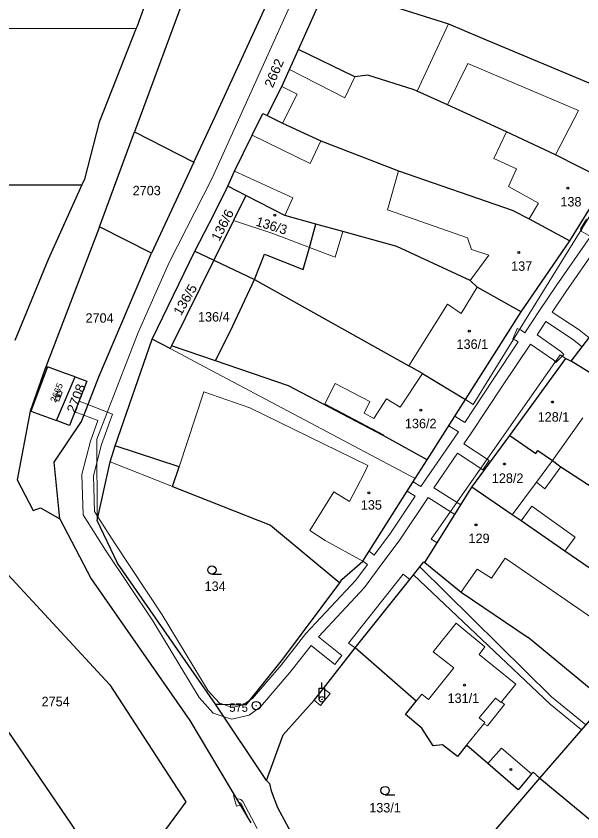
# Model space of a CAD drawing. Extents: x -606517 to -602431, y -1183120 to -1179397.
# Drawn here: x -605631 to -605529.1, y -1181145.3 to -1181000.2 of the extents above; entities that cross this region are included whole.
import ezdxf
from ezdxf.enums import TextEntityAlignment as Align

# ---------------------------------------------------------------- set-up
doc = ezdxf.new("R2010")
doc.units = 0
doc.header["$LTSCALE"] = 0.68
for name, color, linetype, lineweight in [('1', 7, 'Continuous', 25), ('13', 7, 'Continuous', 13), ('3', 7, 'Continuous', 25), ('4', 7, 'Continuous', 13), ('5', 7, 'Continuous', 25), ('6', 7, 'Continuous', 25), ('8', 7, 'Continuous', 25)]:
    doc.layers.add(name, color=color, linetype=linetype, lineweight=lineweight)
doc.layers.add('2', color=7, linetype='Continuous')

msp = doc.modelspace()

# ---------------------------------------------------------------- linework, layer by layer
at = {"layer": '1'}
for p, q in [((-605599.33, -1180975.13), (-605609.21, -1181002.01)), ((-605596.9, -1180986.39), (-605609.67, -1181021.03)), ((-605595.15, -1181018.31), (-605580.95, -1180987.38)), ((-605580.12, -1181006.24), (-605574.98, -1180994.69)), ((-605574.98, -1180994.69), (-605553.1, -1181001.62)), ((-605553.1, -1181001.62), (-605547.49, -1181004.03)), ((-605776.96, -1181002.53), (-605609.37, -1181002.41)), ((-605609.37, -1181002.41), (-605616.01, -1181019.28)), ((-605609.21, -1181002.01), (-605609.37, -1181002.41)), ((-605547.49, -1181004.03), (-605524.08, -1181013.81)), ((-605581.77, -1181009.85), (-605580.12, -1181006.24)), ((-605570.02, -1181011.17), (-605580.12, -1181006.24)), ((-605583.12, -1181012.9), (-605581.77, -1181009.85)), ((-605567.66, -1181010.84), (-605570.02, -1181011.17)), ((-605559.28, -1181013.49), (-605567.66, -1181010.84)), ((-605585.76, -1181018.1), (-605583.12, -1181012.9)), ((-605558.75, -1181013.72), (-605559.28, -1181013.49)), ((-605553.29, -1181016.16), (-605558.75, -1181013.72)), ((-605542.68, -1181021.07), (-605553.29, -1181016.16)), ((-605588.49, -1181021.64), (-605586.54, -1181017.75)), ((-605586.54, -1181017.75), (-605585.76, -1181018.1)), ((-605598.96, -1181026.49), (-605595.15, -1181018.31)), ((-605585.76, -1181018.1), (-605583, -1181019.51)), ((-605616.01, -1181019.28), (-605618.69, -1181029.59)), ((-605583, -1181019.51), (-605576.12, -1181022.66)), ((-605615.97, -1181038.14), (-605609.67, -1181021.03)), ((-605609.67, -1181021.03), (-605598.96, -1181026.49)), ((-605591.63, -1181028.13), (-605588.49, -1181021.64)), ((-605533.83, -1181025.16), (-605542.68, -1181021.07)), ((-605576.12, -1181022.66), (-605562.12, -1181028.07)), ((-605524.63, -1181029.91), (-605533.83, -1181025.16)), ((-605598.96, -1181026.49), (-605606.63, -1181042.91)), ((-605592.83, -1181030.86), (-605591.63, -1181028.13)), ((-605562.12, -1181028.07), (-605541.67, -1181035.14)), ((-605782.99, -1181030.62), (-605619.15, -1181030.62)), ((-605619.15, -1181030.62), (-605625.2, -1181044.06)), ((-605618.69, -1181029.59), (-605619.15, -1181030.62)), ((-605531.26, -1181040.68), (-605524.63, -1181029.91)), ((-605595.34, -1181035.82), (-605592.83, -1181030.86)), ((-605589.63, -1181032.5), (-605592.83, -1181030.86)), ((-605589.63, -1181032.5), (-605591.85, -1181036.99)), ((-605582.6, -1181036.1), (-605589.63, -1181032.5)), ((-605541.67, -1181035.14), (-605538.61, -1181036.71)), ((-605598.8, -1181042.55), (-605595.34, -1181035.82)), ((-605577.01, -1181037.66), (-605582.6, -1181036.1)), ((-605591.85, -1181036.99), (-605595.4, -1181044.16)), ((-605578.18, -1181041.87), (-605577.01, -1181037.66)), ((-605572.16, -1181039.02), (-605577.01, -1181037.66)), ((-605538.61, -1181036.71), (-605531.26, -1181040.68)), ((-605615.97, -1181038.14), (-605625.82, -1181063.83)), ((-605606.63, -1181042.91), (-605615.97, -1181038.14)), ((-605562.4, -1181041.67), (-605572.16, -1181039.02)), ((-605540.05, -1181053.45), (-605531.26, -1181040.68)), ((-605579.28, -1181045.84), (-605578.18, -1181041.87)), ((-605549.25, -1181047.83), (-605562.4, -1181041.67)), ((-605616.1, -1181065.17), (-605606.63, -1181042.91)), ((-605606.46, -1181058.38), (-605598.8, -1181042.55)), ((-605598.8, -1181042.55), (-605595.4, -1181044.16)), ((-605588.05, -1181047.65), (-605586.23, -1181043.1)), ((-605586.23, -1181043.1), (-605579.28, -1181045.84)), ((-605625.2, -1181044.06), (-605631.19, -1181058.61)), ((-605595.4, -1181044.16), (-605603.02, -1181059.57)), ((-605595.4, -1181044.16), (-605588.05, -1181047.65)), ((-605591.97, -1181055.99), (-605588.05, -1181047.65)), ((-605588.05, -1181047.65), (-605560.25, -1181063.15)), ((-605547.99, -1181049.04), (-605549.25, -1181047.83)), ((-605540.05, -1181053.45), (-605547.99, -1181049.04)), ((-605531.03, -1181062.35), (-605522.41, -1181051.06)), ((-605550.05, -1181069.21), (-605540.05, -1181053.45)), ((-605595.1, -1181062.3), (-605591.97, -1181055.99)), ((-605613.14, -1181077.56), (-605606.46, -1181058.38)), ((-605603.27, -1181060.07), (-605606.46, -1181058.38)), ((-605603.02, -1181059.57), (-605603.27, -1181060.07)), ((-605595.1, -1181062.3), (-605603.02, -1181059.57)), ((-605581.95, -1181066.79), (-605595.1, -1181062.3)), ((-605542.07, -1181075.72), (-605532, -1181061.87)), ((-605532, -1181061.87), (-605531.03, -1181062.35)), ((-605524.21, -1181066.58), (-605531.03, -1181062.35)), ((-605625.82, -1181063.83), (-605628.47, -1181071.36)), ((-605557.78, -1181064.57), (-605560.25, -1181063.15)), ((-605623.72, -1181073.02), (-605620.35, -1181065.17)), ((-605620.35, -1181065.17), (-605618.26, -1181065.94)), ((-605619.22, -1181073.19), (-605616.1, -1181065.17)), ((-605557.78, -1181064.57), (-605550.05, -1181069.21)), ((-605618.26, -1181065.94), (-605621.35, -1181073.9)), ((-605564.9, -1181075.72), (-605581.95, -1181066.79)), ((-605556.96, -1181080.1), (-605550.05, -1181069.21)), ((-605628.47, -1181071.36), (-605630.77, -1181083.68)), ((-605624.1, -1181080.55), (-605619.22, -1181073.19)), ((-605621.35, -1181073.9), (-605623.72, -1181073.02)), ((-605556.96, -1181080.1), (-605564.9, -1181075.72)), ((-605548.91, -1181085.05), (-605542.07, -1181075.72)), ((-605542.07, -1181075.72), (-605537.42, -1181078.99)), ((-605614.06, -1181080.48), (-605613.14, -1181077.56)), ((-605601.63, -1181081.38), (-605613.14, -1181077.56)), ((-605537.42, -1181078.99), (-605537.02, -1181078.41)), ((-605537.02, -1181078.41), (-605534.4, -1181080.25)), ((-605559.11, -1181083.48), (-605556.96, -1181080.1)), ((-605623.1, -1181090.74), (-605624.1, -1181080.55)), ((-605616.4, -1181091.03), (-605614.06, -1181080.48)), ((-605602.8, -1181084.92), (-605601.63, -1181081.38)), ((-605534.4, -1181080.25), (-605532.92, -1181081.39)), ((-605532.92, -1181081.39), (-605517.36, -1181091.51)), ((-605630.77, -1181083.68), (-605627.9, -1181089.24)), ((-605568.55, -1181098.33), (-605559.11, -1181083.48)), ((-605602.8, -1181084.92), (-605585.17, -1181091.89)), ((-605555.15, -1181095.07), (-605548.91, -1181085.05)), ((-605541.68, -1181090.01), (-605548.91, -1181085.05)), ((-605627.9, -1181089.24), (-605626.6, -1181088.77)), ((-605626.6, -1181088.77), (-605623.1, -1181090.74)), ((-605540.41, -1181090.83), (-605541.68, -1181090.01)), ((-605623.1, -1181090.74), (-605617.47, -1181101.51)), ((-605612.7, -1181098.73), (-605616.4, -1181091.03)), ((-605540.06, -1181091.07), (-605540.41, -1181090.83)), ((-605532.17, -1181096.53), (-605540.06, -1181091.07)), ((-605585.17, -1181091.89), (-605572.68, -1181102.22)), ((-605572.61, -1181216.57), (-605656.78, -1181093.27)), ((-605557.36, -1181098.61), (-605555.15, -1181095.07)), ((-605524.68, -1181101.71), (-605532.17, -1181096.53)), ((-605595.06, -1181124.07), (-605612.7, -1181098.73)), ((-605572.35, -1181101.66), (-605568.55, -1181098.33)), ((-605560.1, -1181101.65), (-605557.57, -1181098.48)), ((-605557.57, -1181098.48), (-605557.36, -1181098.61)), ((-605557.36, -1181098.61), (-605550.82, -1181103.9)), ((-605633.2, -1181099.97), (-605614.08, -1181120.62)), ((-605617.47, -1181101.51), (-605599.71, -1181127.02)), ((-605572.68, -1181102.22), (-605572.35, -1181101.66)), ((-605569.94, -1181113.96), (-605560.1, -1181101.65)), ((-605582.98, -1181115.96), (-605572.68, -1181102.22)), ((-605550.82, -1181103.9), (-605538.79, -1181112.11)), ((-605524.79, -1181123.67), (-605538.79, -1181112.11)), ((-605575.63, -1181121.25), (-605569.94, -1181113.96)), ((-605558.93, -1181123.55), (-605569.94, -1181113.96)), ((-605589.54, -1181124.22), (-605582.98, -1181115.96)), ((-605614.08, -1181120.62), (-605600.45, -1181141.66)), ((-605577.33, -1181123.36), (-605575.63, -1181121.25)), ((-605582.89, -1181129.61), (-605577.33, -1181123.36)), ((-605536.65, -1181137.41), (-605524.79, -1181123.67)), ((-605585.88, -1181137.84), (-605595.06, -1181124.07)), ((-605595.06, -1181124.07), (-605589.54, -1181124.22)), ((-605599.71, -1181127.02), (-605588.69, -1181145.43)), ((-605585.88, -1181137.84), (-605582.89, -1181129.61)), ((-605546.03, -1181134.8), (-605549.86, -1181131.46)), ((-605540.59, -1181139.54), (-605546.03, -1181134.8)), ((-605538.17, -1181136.64), (-605540.59, -1181139.54)), ((-605537.9, -1181136.34), (-605538.17, -1181136.64)), ((-605537.9, -1181136.34), (-605536.65, -1181137.41)), ((-605585.38, -1181138.39), (-605585.88, -1181137.84)), ((-605566.67, -1181172.2), (-605536.65, -1181137.41)), ((-605536.65, -1181137.41), (-605527.3, -1181145.14)), ((-605585.38, -1181138.39), (-605585.04, -1181139.67)), ((-605585.04, -1181139.67), (-605583.91, -1181142.7)), ((-605600.45, -1181141.66), (-605611.43, -1181156.66)), ((-605583.91, -1181142.7), (-605578.24, -1181153.14))]:
    msp.add_line(p, q, dxfattribs=at)
for points in [[(-605620.35, -1181065.17), (-605622.09, -1181064.54), (-605625.3, -1181063.36), (-605628.33, -1181071.31), (-605623.72, -1181073.02)], [(-605549.86, -1181131.46), (-605551.52, -1181133.53), (-605554.19, -1181131.42), (-605555.87, -1181131.57), (-605557.91, -1181128.39), (-605560.88, -1181125.96), (-605558.93, -1181123.55)]]:
    msp.add_lwpolyline(points, dxfattribs=at)
at = {"layer": '13'}
for points in [[(-605528.27, -1181036.8), (-605529.37, -1181038.52), (-605529.09, -1181038.7), (-605529.26, -1181038.94), (-605527.56, -1181039.91), (-605533.74, -1181048.76), (-605536.74, -1181053.19), (-605539.4, -1181057.22), (-605540.06, -1181056.77), (-605540.74, -1181056.48), (-605541.54, -1181058.36), (-605541.04, -1181058.57), (-605540.59, -1181058.88), (-605545.11, -1181065.64), (-605550.21, -1181073.36), (-605551.97, -1181072.24), (-605553.06, -1181073.96), (-605551.35, -1181075.06), (-605552.79, -1181077.15), (-605558.12, -1181084.91), (-605559.47, -1181084.05), (-605560.56, -1181085.77), (-605559.14, -1181086.66), (-605563.59, -1181093.29), (-605566.52, -1181097.29), (-605567.42, -1181096.56), (-605568.55, -1181098.33), (-605567.73, -1181098.93), (-605569.81, -1181101.78), (-605578.79, -1181111.38), (-605583.26, -1181117.05), (-605588.39, -1181123.07), (-605588.88, -1181123.39), (-605589.54, -1181124.22), (-605590.12, -1181124.2), (-605592.06, -1181124.67), (-605593.78, -1181124.1), (-605595.06, -1181124.07), (-605612.7, -1181098.73), (-605616.4, -1181091.03), (-605616.25, -1181090.35), (-605616.86, -1181089.39), (-605617.06, -1181082.99), (-605615.62, -1181077.32), (-605613.65, -1181071.89), (-605618.04, -1181070.16), (-605619.65, -1181069.52), (-605620.39, -1181071.43), (-605618.78, -1181072.06), (-605616.27, -1181073.05), (-605617.6, -1181076.72), (-605619.12, -1181082.77), (-605618.9, -1181090.01), (-605614.86, -1181096.39), (-605606.39, -1181109.11), (-605598.03, -1181122.91), (-605595.5, -1181125.7), (-605593.54, -1181126.35), (-605592.16, -1181126.81), (-605589.01, -1181126.05)], [(-605527.81, -1181058.14), (-605529.62, -1181056.7), (-605534.47, -1181053.5), (-605532, -1181049.86), (-605526.39, -1181041.82)], [(-605589.01, -1181126.05), (-605586.99, -1181124.59), (-605581.68, -1181118.37), (-605577.84, -1181113.51), (-605573.61, -1181116.93), (-605572.33, -1181115.35), (-605576.51, -1181111.97), (-605568.23, -1181103.1), (-605565.6, -1181099.51), (-605561.91, -1181094.49), (-605556.81, -1181086.89), (-605551.96, -1181089.95), (-605550.89, -1181088.23), (-605555.78, -1181085.14), (-605551.5, -1181078.9), (-605546.92, -1181081.92), (-605545.8, -1181080.22), (-605550.34, -1181077.23), (-605549.03, -1181075.33), (-605543.39, -1181066.78), (-605538.36, -1181059.27), (-605534.17, -1181062.17), (-605533.77, -1181062.57), (-605532.33, -1181061.13), (-605532.87, -1181060.59), (-605537.19, -1181057.6), (-605535.61, -1181055.19), (-605530.82, -1181058.36), (-605529.05, -1181059.75)], [(-605587.58, -1181146.47), (-605590.13, -1181141.61), (-605590.54, -1181141.25), (-605591.31, -1181141.05), (-605590.94, -1181141.66), (-605590.53, -1181141.93), (-605588.69, -1181145.43)]]:
    msp.add_lwpolyline(points, dxfattribs=at)
for points in [[(-605616.25, -1181090.35), (-605616.4, -1181091.03), (-605612.7, -1181098.73), (-605595.06, -1181124.07), (-605593.78, -1181124.1), (-605594.34, -1181123.92), (-605596.37, -1181121.67), (-605604.67, -1181107.99), (-605613.14, -1181095.25)], [(-605558.26, -1181099.34), (-605559.42, -1181100.8), (-605534.81, -1181124.08), (-605529.15, -1181128.72), (-605528.4, -1181127.84), (-605534.58, -1181122.76)], [(-605590.12, -1181124.2), (-605589.54, -1181124.22), (-605588.88, -1181123.39)], [(-605590.59, -1181142.25), (-605590.94, -1181141.66), (-605591.31, -1181141.05), (-605591.66, -1181140.47), (-605591.81, -1181140.52), (-605591.27, -1181142.44)]]:
    msp.add_lwpolyline(points, close=True, dxfattribs=at)
at = {"layer": '3'}
for p, q in [((-605595.723, -1181100.68), (-605593.973, -1181100.68)), ((-605564.543, -1181140.4), (-605562.793, -1181140.4))]:
    msp.add_line(p, q, dxfattribs=at)
for centre in [(-605595.7229, -1181099.9298), (-605564.5429, -1181139.6498)]:
    msp.add_circle(centre, 0.75, dxfattribs=at)
at = {"layer": '4'}
for p, q in [((-605558.75, -1181013.72), (-605553.1, -1181001.62)), ((-605549.67, -1181008.77), (-605553.29, -1181016.16)), ((-605529.72, -1181017.2), (-605549.67, -1181008.77)), ((-605571.81, -1181014.91), (-605581.77, -1181009.85)), ((-605570.02, -1181011.17), (-605571.81, -1181014.91)), ((-605583.12, -1181012.9), (-605580.38, -1181014.29)), ((-605580.38, -1181014.29), (-605583, -1181019.51)), ((-605548.7, -1181070.14), (-605516.22, -1181017.62)), ((-605533.83, -1181025.16), (-605529.72, -1181017.2)), ((-605588.49, -1181021.64), (-605578.05, -1181026.75)), ((-605544.97, -1181025.86), (-605542.68, -1181021.07)), ((-605578.05, -1181026.75), (-605576.12, -1181022.66)), ((-605540.91, -1181027.72), (-605544.97, -1181025.86)), ((-605542.34, -1181030.9), (-605540.91, -1181027.72)), ((-605581.15, -1181032.94), (-605591.63, -1181028.13)), ((-605564.08, -1181035.11), (-605562.12, -1181028.07)), ((-605536.9, -1181033.89), (-605542.34, -1181030.9)), ((-605582.6, -1181036.1), (-605581.15, -1181032.94)), ((-605549.68, -1181040.13), (-605564.08, -1181035.11)), ((-605538.61, -1181036.71), (-605536.9, -1181033.89)), ((-605591.85, -1181036.99), (-605584.74, -1181039.38)), ((-605584.74, -1181039.38), (-605578.18, -1181041.87)), ((-605573.53, -1181043.64), (-605572.16, -1181039.02)), ((-605548.96, -1181042.25), (-605549.68, -1181040.13)), ((-605578.18, -1181041.87), (-605573.53, -1181043.64)), ((-605545.85, -1181043.28), (-605548.96, -1181042.25)), ((-605549.25, -1181047.83), (-605545.85, -1181043.28)), ((-605550.86, -1181053.73), (-605547.99, -1181049.04)), ((-605560.25, -1181063.15), (-605553.31, -1181052.05)), ((-605553.31, -1181052.05), (-605550.86, -1181053.73)), ((-605556.25, -1181094.4), (-605533.02, -1181061.2)), ((-605533.02, -1181061.2), (-605532, -1181061.87)), ((-605557.78, -1181064.57), (-605561.83, -1181070.61)), ((-605567.28, -1181069.62), (-605573.53, -1181066.35)), ((-605597.17, -1181067.86), (-605601.63, -1181081.38)), ((-605588.9, -1181070.71), (-605597.17, -1181067.86)), ((-605568.31, -1181071.7), (-605567.28, -1181069.62)), ((-605566.55, -1181072.66), (-605564.29, -1181069.09)), ((-605564.29, -1181069.09), (-605561.83, -1181070.61)), ((-605550.05, -1181069.21), (-605548.7, -1181070.14)), ((-605588.9, -1181070.71), (-605567.63, -1181081.15)), ((-605568.31, -1181071.7), (-605566.55, -1181072.66)), ((-605534.4, -1181080.25), (-605528.93, -1181072.52)), ((-605564.9, -1181075.72), (-605564.82, -1181075.59)), ((-605614.06, -1181080.48), (-605602.8, -1181084.92)), ((-605568.34, -1181082.54), (-605567.63, -1181081.15)), ((-605537.31, -1181084.15), (-605534.4, -1181080.25)), ((-605535.76, -1181085.31), (-605532.92, -1181081.39)), ((-605570.93, -1181087.6), (-605568.34, -1181082.54)), ((-605541.68, -1181090.01), (-605537.31, -1181084.15)), ((-605537.31, -1181084.15), (-605535.76, -1181085.31)), ((-605578.09, -1181092.84), (-605573.76, -1181085.87)), ((-605573.76, -1181085.87), (-605570.93, -1181087.6)), ((-605538.11, -1181088.44), (-605540.06, -1181091.07)), ((-605530.52, -1181093.91), (-605538.11, -1181088.44)), ((-605575.34, -1181094.6), (-605578.09, -1181092.84)), ((-605568.55, -1181098.33), (-605575.34, -1181094.6)), ((-605556.25, -1181094.4), (-605555.15, -1181095.07)), ((-605532.17, -1181096.53), (-605530.31, -1181094.05)), ((-605530.31, -1181094.05), (-605530.52, -1181093.91)), ((-605545.4, -1181101.39), (-605542.91, -1181097.79)), ((-605542.91, -1181097.79), (-605526.18, -1181109.35)), ((-605550.36, -1181103.23), (-605547.95, -1181099.78)), ((-605547.95, -1181099.78), (-605545.4, -1181101.39)), ((-605571.14, -1181113.1), (-605561.28, -1181100.7)), ((-605561.28, -1181100.7), (-605560.1, -1181101.65)), ((-605550.82, -1181103.9), (-605550.36, -1181103.23)), ((-605569.94, -1181113.96), (-605571.14, -1181113.1)), ((-605576.16, -1181124.31), (-605574.45, -1181122.2)), ((-605574.45, -1181122.2), (-605575.63, -1181121.25)), ((-605577.33, -1181123.36), (-605576.16, -1181124.31)), ((-605546.75, -1181127.61), (-605549.86, -1181131.46)), ((-605546.03, -1181134.8), (-605543.59, -1181132.02)), ((-605543.59, -1181132.02), (-605538.17, -1181136.64))]:
    msp.add_line(p, q, dxfattribs=at)
for points in [[(-605616.4, -1181091.03), (-605616.44, -1181076.41), (-605608.98, -1181057.17), (-605603.42, -1181044.56), (-605595.68, -1181029.4), (-605579.16, -1180992.77), (-605569.81, -1180969.9), (-605559.25, -1180938.77), (-605553.42, -1180922.56)], [(-605603.27, -1181060.07), (-605595.92, -1181063.96), (-605559.11, -1181083.48)], [(-605564.82, -1181075.59), (-605575.41, -1181069.99), (-605573.53, -1181066.35)], [(-605558.93, -1181123.55), (-605557.9, -1181122.27), (-605556.7, -1181123.25), (-605552.16, -1181117.56), (-605555.89, -1181114.65), (-605551.74, -1181109.49), (-605546.57, -1181113.75), (-605547.63, -1181115.17), (-605541.02, -1181120.51), (-605543.58, -1181123.69)], [(-605543.58, -1181123.69), (-605543.67, -1181123.79), (-605544.64, -1181122.99), (-605547.58, -1181126.58), (-605546.57, -1181127.37), (-605546.75, -1181127.61)], [(-605546.75, -1181127.61), (-605546.09, -1181128.02), (-605543.02, -1181124.14), (-605543.58, -1181123.69)]]:
    msp.add_lwpolyline(points, dxfattribs=at)
msp.add_lwpolyline([(-605623.99, -1181069.3), (-605623.38, -1181067.66), (-605622.7, -1181067.92), (-605623.3, -1181069.55)], close=True, dxfattribs=at)
at = {"layer": '5'}
for centre in [(-605531.6368, -1181031.2092), (-605584.4068, -1181036.0292), (-605540.4868, -1181042.7892), (-605549.3768, -1181056.9192), (-605623.3068, -1181068.5692), (-605534.3768, -1181069.6892), (-605558.1268, -1181071.1392), (-605543.0368, -1181080.8492), (-605567.4468, -1181086.0392), (-605548.1768, -1181091.8192), (-605550.2668, -1181120.6492), (-605541.8853, -1181135.875)]:
    msp.add_circle(centre, 0.175, dxfattribs=at)
at = {"layer": '6'}
for p, q in [((-605575.92, -1181121.206), (-605575.92, -1181120.206)), ((-605576.42, -1181121.206), (-605575.42, -1181121.206)), ((-605576.42, -1181123.206), (-605576.42, -1181121.206)), ((-605575.42, -1181123.206), (-605575.42, -1181121.206))]:
    msp.add_line(p, q, dxfattribs=at)
for radius in [0.5, 0.0303]:
    msp.add_circle((-605575.92, -1181123.2076), radius, dxfattribs=at)
at = {"layer": '8'}
for radius in [0.75, 0.03]:
    msp.add_circle((-605587.75, -1181124.3498), radius, dxfattribs=at)

# ---------------------------------------------------------------- texts
at = {"layer": '2', "width": 1.05}
for s, rotation, p in [('2662', 67, (-605584.778, -1181013.246)), ('136/5', 60, (-605601.301, -1181054.272)), ('2708', 69, (-605620.343, -1181071.812))]:
    msp.add_text(s, height=1.7, rotation=rotation, dxfattribs=at).set_placement(p)
at = {"layer": '2'}
for s, p in [('2703', (-605609.99, -1181032.475)), ('138', (-605532.98, -1181034.485)), ('137', (-605541.84, -1181046.065)), ('2704', (-605618.48, -1181055.415)), ('136/1', (-605551.68, -1181060.125)), ('128/1', (-605537.07, -1181073.225)), ('136/2', (-605560.97, -1181074.415)), ('128/2', (-605545.32, -1181084.255)), ('135', (-605568.91, -1181089.065)), ('129', (-605549.52, -1181095.085)), ('134', (-605597.04, -1181103.705)), ('2754', (-605626.39, -1181124.465))]:
    msp.add_text(s, height=1.7, dxfattribs=at).set_placement(p)
at = {"layer": '2', "width": 1.05}
for s, height, rotation, p in [('136/6', 1.7, 63, (-605593.0565, -1181038.2159)), ('2665', 1.139, 68, (-605623.1714, -1181068.2173))]:
    msp.add_text(s, height=height, rotation=rotation, dxfattribs=at).set_placement(p, align=Align.CENTER)
at = {"layer": '2'}
msp.add_text('136/3', height=1.7, rotation=343, dxfattribs=at).set_placement((-605587.934, -1181037.916))
for s, p in [('136/4', (-605595.38, -1181055.205)), ('131/1', (-605550.45, -1181123.865)), ('133/1', (-605564.55, -1181143.585))]:
    msp.add_text(s, height=1.7, dxfattribs=at).set_placement(p, align=Align.CENTER)
at = {"layer": '8'}
msp.add_text('575', height=1.5, dxfattribs=at).set_placement((-605589.249, -1181125.467), align=Align.RIGHT)

doc.saveas('drawing.dxf')
